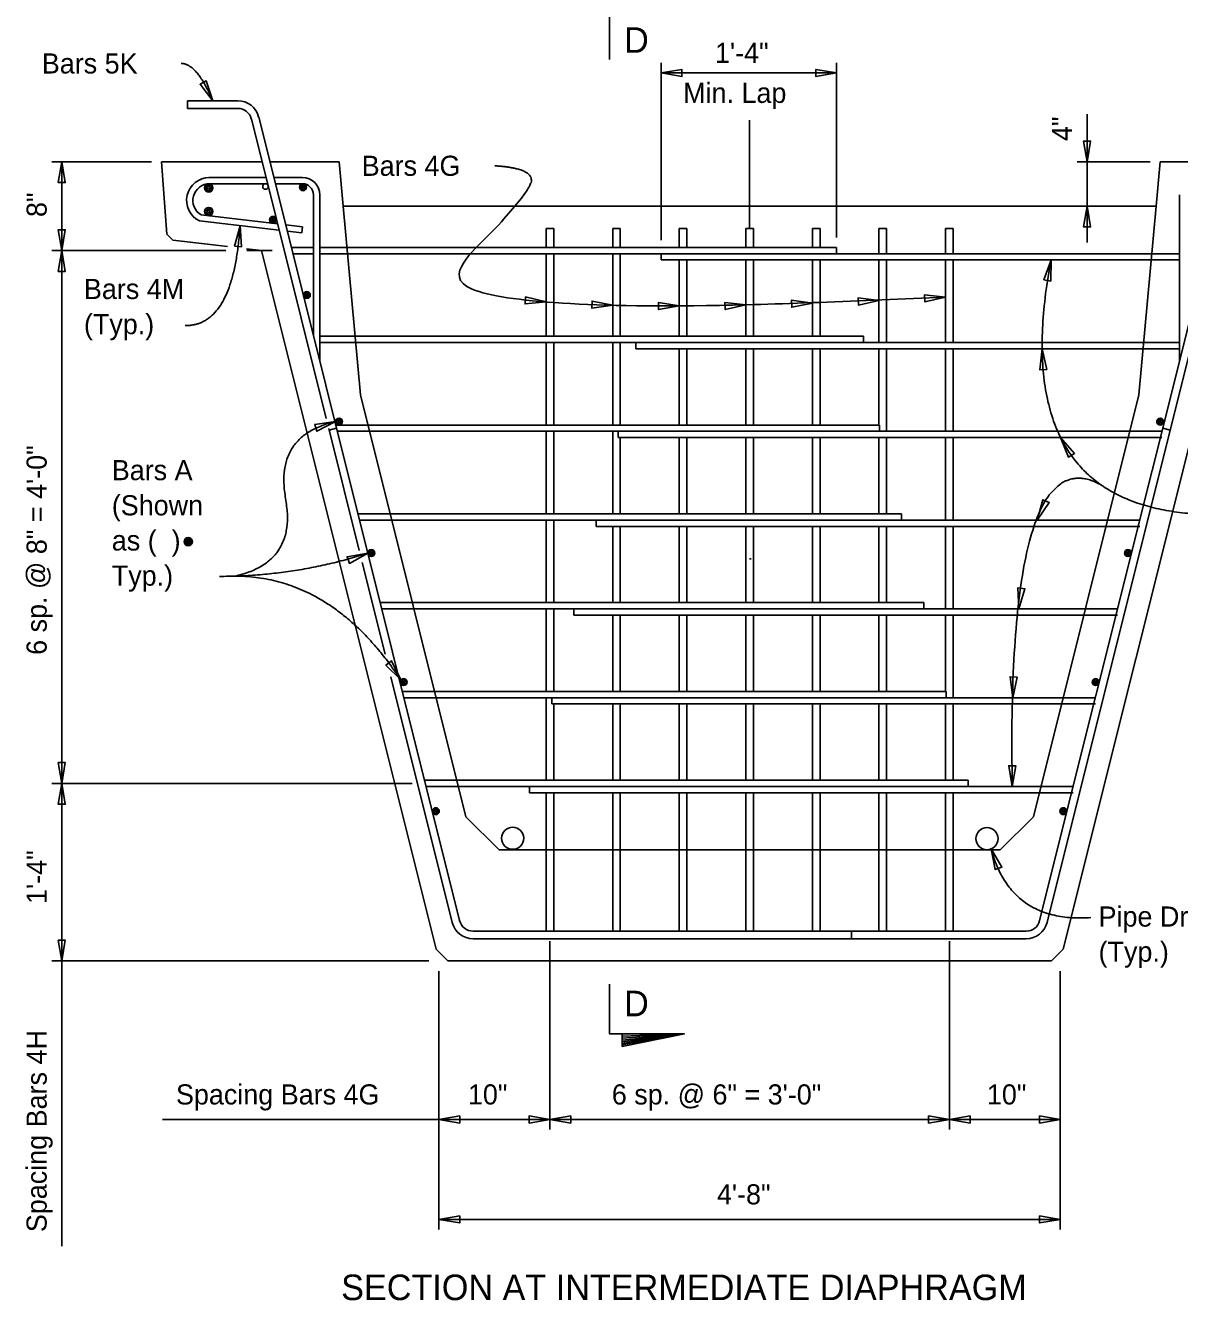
# Model space of a CAD drawing. Extents: x 120693.4 to 120747.1, y 120647.1 to 120670.1.
# Drawn here: x 120693.43 to 120702.1, y 120652.17 to 120661.74 of the extents above; entities that cross this region are included whole.
import ezdxf

# ---------------------------------------------------------------- set-up
doc = ezdxf.new("R2010")
doc.units = 0
for name, color, linetype in [('BeamConc', 7, 'Continuous'), ('BeamConc_h', 7, 'Continuous'), ('CL_Major', 7, 'Continuous'), ('Dimension', 7, 'Continuous'), ('Miscellaneous', 7, 'Continuous'), ('Rebar', 7, 'Continuous'), ('TextStructures', 7, 'Continuous')]:
    doc.layers.add(name, color=color, linetype=linetype)

msp = doc.modelspace()

# ---------------------------------------------------------------- linework, layer by layer
at = {"layer": 'BeamConc'}
for p, q in [((120694.456, 120660.7178), (120694.4948, 120660.1751)), ((120694.456, 120660.7178), (120695.2111, 120660.7178)), ((120695.2702, 120660.7178), (120695.7893, 120660.7178)), ((120695.8198, 120660.3845), (120695.7893, 120660.7178)), ((120701.9255, 120660.3845), (120701.956, 120660.7178)), ((120701.956, 120660.7178), (120702.4751, 120660.7178)), ((120695.8198, 120660.3845), (120701.9255, 120660.3845)), ((120694.5404, 120660.1294), (120694.4948, 120660.1751)), ((120694.5404, 120660.1294), (120694.9505, 120660.0812)), ((120695.0946, 120660.0642), (120695.206, 120660.0511)), ((120696.5172, 120654.8062), (120695.206, 120660.0511)), ((120701.2281, 120654.8062), (120702.5393, 120660.0511)), ((120696.6056, 120654.7178), (120696.5172, 120654.8062)), ((120701.1397, 120654.7178), (120701.2281, 120654.8062)), ((120696.6056, 120654.7178), (120701.1397, 120654.7178))]:
    msp.add_line(p, q, dxfattribs=at)
at = {"layer": 'BeamConc_h'}
for p, q in [((120695.9493, 120658.9678), (120695.8198, 120660.3845)), ((120701.7961, 120658.9678), (120701.9255, 120660.3845)), ((120696.7409, 120655.8011), (120695.9493, 120658.9678)), ((120701.0044, 120655.8011), (120701.7961, 120658.9678)), ((120696.7409, 120655.8011), (120696.9909, 120655.5511)), ((120701.0044, 120655.8011), (120700.7544, 120655.5511)), ((120696.9909, 120655.5511), (120700.7544, 120655.5511))]:
    msp.add_line(p, q, dxfattribs=at)
at = {"layer": 'CL_Major'}
for p, q in [((120698.8727, 120660.2178), (120698.8727, 120661.0292)), ((120698.8727, 120657.7357), (120698.885, 120657.7357))]:
    msp.add_line(p, q, dxfattribs=at)
at = {"layer": 'Dimension'}
for p, q in [((120698.2086, 120660.1281), (120698.2086, 120661.4601)), ((120699.5261, 120660.1502), (120699.5261, 120661.4601)), ((120698.2086, 120661.3845), (120699.5261, 120661.3845)), ((120701.4076, 120661.0752), (120701.4076, 120660.1113)), ((120694.3804, 120660.7178), (120693.6304, 120660.7178)), ((120693.706, 120660.7178), (120693.706, 120652.5766)), ((120701.8804, 120660.7178), (120701.3319, 120660.7178)), ((120694.9389, 120660.0511), (120693.6304, 120660.0511)), ((120695.2856, 120660.0511), (120695.0951, 120660.0511)), ((120696.3376, 120656.0511), (120693.6304, 120656.0511)), ((120697.3726, 120654.8661), (120697.3726, 120653.4522)), ((120700.3726, 120654.8661), (120700.3726, 120653.4522)), ((120696.4637, 120654.7178), (120693.6304, 120654.7178)), ((120696.5393, 120654.6421), (120696.5393, 120652.7022)), ((120701.206, 120654.6421), (120701.206, 120652.7022)), ((120697.914, 120654.1523), (120698.3827, 120654.1698)), ((120698.3827, 120654.1698), (120697.914, 120654.1373)), ((120697.914, 120654.1235), (120698.3827, 120654.1698)), ((120698.3827, 120654.1698), (120697.914, 120654.1098)), ((120697.914, 120654.0973), (120698.3827, 120654.1698)), ((120698.3827, 120654.1698), (120697.914, 120654.0873)), ((120694.4617, 120653.5278), (120701.206, 120653.5278)), ((120696.5393, 120652.7779), (120701.206, 120652.7779))]:
    msp.add_line(p, q, dxfattribs=at)
for points in [[(120697.8202, 120661.4861), (120697.8202, 120661.8611), (120698.3827, 120661.8611), (120697.914, 120661.9548), (120697.914, 120661.8611)], [(120697.8202, 120654.5448), (120697.8202, 120654.1698), (120698.3827, 120654.1698), (120697.914, 120654.076), (120697.914, 120654.1698)]]:
    msp.add_lwpolyline(points, dxfattribs=at)
for points in [[(120698.2085, 120661.3845), (120698.3642, 120661.3578), (120698.3642, 120661.4111)], [(120699.526, 120661.3845), (120699.3704, 120661.4111), (120699.3704, 120661.3578)], [(120694.8418, 120661.175), (120694.7444, 120661.2999), (120694.791, 120661.325)], [(120701.4072, 120660.7176), (120701.4339, 120660.8732), (120701.3806, 120660.8732)], [(120693.706, 120660.7177), (120693.6796, 120660.5615), (120693.7325, 120660.5615)], [(120701.4072, 120660.3843), (120701.3806, 120660.2286), (120701.4339, 120660.2286)], [(120693.706, 120660.0512), (120693.6796, 120660.2074), (120693.7325, 120660.2074)], [(120695.0456, 120660.2377), (120695.0565, 120660.0797), (120695.0038, 120660.0849)], [(120693.706, 120660.051), (120693.6796, 120659.8949), (120693.7325, 120659.8949)], [(120701.1366, 120659.9807), (120701.0828, 120659.8317), (120701.1349, 120659.8223)], [(120697.3441, 120659.6656), (120697.1903, 120659.7035), (120697.1863, 120659.6507)], [(120699.344, 120659.6573), (120699.187, 120659.6784), (120699.1888, 120659.6255)], [(120699.844, 120659.6768), (120699.6866, 120659.6953), (120699.6893, 120659.6424)], [(120700.344, 120659.7006), (120700.1866, 120659.719), (120700.1893, 120659.6662)], [(120697.8441, 120659.6412), (120697.6887, 120659.672), (120697.6872, 120659.6191)], [(120698.3441, 120659.6366), (120698.1875, 120659.6605), (120698.1883, 120659.6076)], [(120698.844, 120659.6432), (120698.6865, 120659.661), (120698.6895, 120659.6081)], [(120701.0697, 120659.3141), (120701.0517, 120659.1567), (120701.1045, 120659.1595)], [(120695.763, 120658.7673), (120695.606, 120658.7457), (120695.6219, 120658.6952)], [(120701.2084, 120658.6474), (120701.2675, 120658.5004), (120701.3126, 120658.528)], [(120701.0335, 120658.0278), (120701.1227, 120658.1587), (120701.0746, 120658.1808)], [(120696.0052, 120657.7801), (120695.8491, 120657.7529), (120695.8668, 120657.703)], [(120700.894, 120657.3611), (120700.9398, 120657.5127), (120700.8873, 120657.5194)], [(120696.253, 120656.8279), (120696.1832, 120656.9701), (120696.1403, 120656.9391)], [(120700.85, 120656.6944), (120700.8815, 120656.8496), (120700.8286, 120656.8513)], [(120693.706, 120656.0512), (120693.6796, 120656.2074), (120693.7325, 120656.2074)], [(120700.8448, 120656.0277), (120700.8714, 120656.1839), (120700.8185, 120656.1839)], [(120693.706, 120656.051), (120693.6796, 120655.8949), (120693.7325, 120655.8949)], [(120700.6871, 120655.5597), (120700.7674, 120655.4231), (120700.7179, 120655.4043)], [(120693.706, 120654.7177), (120693.7325, 120654.8739), (120693.6796, 120654.8739)], [(120696.539, 120653.5276), (120696.6947, 120653.5009), (120696.6947, 120653.5543)], [(120697.3727, 120653.5278), (120697.2165, 120653.5542), (120697.2165, 120653.5013)], [(120697.3726, 120653.5278), (120697.5288, 120653.5542), (120697.5288, 120653.5013)], [(120700.3727, 120653.5278), (120700.2165, 120653.5542), (120700.2165, 120653.5013)], [(120700.3726, 120653.5278), (120700.5288, 120653.5542), (120700.5288, 120653.5013)], [(120701.2057, 120653.5276), (120701.05, 120653.5543), (120701.05, 120653.5009)], [(120696.539, 120652.7777), (120696.6947, 120652.751), (120696.6947, 120652.8043)], [(120701.2057, 120652.7777), (120701.05, 120652.8043), (120701.05, 120652.751)]]:
    msp.add_lwpolyline(points, close=True, dxfattribs=at)
for points in [[(120694.8392, 120661.1761), (120694.721, 120661.4562), (120694.6028, 120661.4562)], [(120700.344, 120659.7006), (120696.2635, 120659.492), (120697.1739, 120660.4306), (120697.2782, 120660.667), (120696.9585, 120660.6879)], [(120695.0451, 120660.2378), (120694.9958, 120659.4842), (120694.6336, 120659.4883)], [(120701.1366, 120659.9808), (120700.7737, 120658.0694), (120702.3784, 120658.0694)], [(120695.0044, 120657.607), (120695.4741, 120657.7086), (120695.3013, 120658.6637), (120695.763, 120658.7673)], [(120700.8448, 120656.0277), (120700.7997, 120658.6696), (120701.5068, 120658.2958)], [(120694.8903, 120657.6052), (120695.4651, 120657.6052), (120696.0052, 120657.7801)], [(120695.0044, 120657.607), (120695.7368, 120657.607), (120696.2531, 120656.8269)], [(120700.6861, 120655.5593), (120700.8388, 120655.0002), (120701.4364, 120655.044)]]:
    msp.add_open_spline(points, degree=2, dxfattribs=at)
at = {"layer": 'Miscellaneous'}
for centre in [(120697.093, 120655.6393), (120700.6551, 120655.6361)]:
    msp.add_circle(centre, 0.0833, dxfattribs=at)
at = {"layer": 'Rebar'}
for p, q in [((120694.6502, 120661.1761), (120695.0282, 120661.1761)), ((120694.6502, 120661.1761), (120694.6502, 120661.1188)), ((120694.6502, 120661.1188), (120695.0282, 120661.1188)), ((120695.6932, 120658.7894), (120695.1305, 120661.0402)), ((120696.6945, 120655.0207), (120695.1861, 120661.0541)), ((120701.0509, 120655.0207), (120702.5605, 120661.059)), ((120701.1064, 120655.0068), (120702.6148, 120661.0402)), ((120695.2406, 120660.5997), (120694.8105, 120660.5997)), ((120695.2524, 120660.5528), (120694.8105, 120660.5528)), ((120695.5137, 120660.5997), (120695.2997, 120660.5997)), ((120695.5137, 120660.5528), (120695.3114, 120660.5528)), ((120695.597, 120659.4105), (120695.597, 120660.4695)), ((120695.6439, 120659.223), (120695.6439, 120660.4695)), ((120702.1015, 120659.223), (120702.1015, 120660.4695)), ((120694.7395, 120660.2738), (120695.3398, 120660.2032)), ((120694.7537, 120660.3193), (120695.3276, 120660.2518)), ((120695.3885, 120660.2446), (120695.5135, 120660.2299)), ((120695.4006, 120660.196), (120695.508, 120660.1834)), ((120695.5135, 120660.2299), (120695.508, 120660.1834)), ((120697.4014, 120660.2178), (120697.3441, 120660.2178)), ((120697.3441, 120660.0746), (120697.3441, 120660.2178)), ((120697.4014, 120660.0746), (120697.4014, 120660.2178)), ((120697.9014, 120660.2178), (120697.8441, 120660.2178)), ((120697.8441, 120660.0746), (120697.8441, 120660.2178)), ((120697.9014, 120660.0746), (120697.9014, 120660.2178)), ((120698.4014, 120660.2178), (120698.3441, 120660.2178)), ((120698.3441, 120660.0746), (120698.3441, 120660.2178)), ((120698.4014, 120660.0746), (120698.4014, 120660.2178)), ((120698.844, 120660.2178), (120698.9013, 120660.2178)), ((120698.844, 120660.0746), (120698.844, 120660.2178)), ((120698.9013, 120660.0746), (120698.9013, 120660.2178)), ((120699.344, 120660.2178), (120699.4013, 120660.2178)), ((120699.344, 120660.0746), (120699.344, 120660.2178)), ((120699.4013, 120660.0746), (120699.4013, 120660.2178)), ((120699.844, 120660.2178), (120699.9013, 120660.2178)), ((120699.844, 120660.0276), (120699.844, 120660.2178)), ((120699.9013, 120660.0276), (120699.9013, 120660.2178)), ((120700.344, 120660.2178), (120700.4013, 120660.2178)), ((120700.344, 120660.0276), (120700.344, 120660.2178)), ((120700.4013, 120660.0276), (120700.4013, 120660.2178)), ((120695.431, 120660.0746), (120695.597, 120660.0746)), ((120695.6439, 120660.0746), (120699.5261, 120660.0746)), ((120699.5261, 120660.0746), (120699.5261, 120660.0276)), ((120695.4427, 120660.0276), (120695.597, 120660.0276)), ((120695.6439, 120660.0276), (120702.1015, 120660.0276)), ((120697.3441, 120659.4079), (120697.3441, 120660.0276)), ((120697.4014, 120659.4079), (120697.4014, 120660.0276)), ((120697.8441, 120659.4079), (120697.8441, 120660.0276)), ((120697.9014, 120659.4079), (120697.9014, 120660.0276)), ((120698.2076, 120660.0277), (120698.2076, 120659.9807)), ((120698.2076, 120659.9807), (120702.1015, 120659.9807)), ((120698.3441, 120659.4079), (120698.3441, 120659.9807)), ((120698.4014, 120659.4079), (120698.4014, 120659.9807)), ((120698.844, 120659.4079), (120698.844, 120659.9807)), ((120698.9013, 120659.4079), (120698.9013, 120659.9807)), ((120699.344, 120659.4079), (120699.344, 120659.9807)), ((120699.4013, 120659.4079), (120699.4013, 120659.9807)), ((120699.844, 120659.3609), (120699.844, 120659.9807)), ((120699.9013, 120659.3609), (120699.9013, 120659.9807)), ((120700.344, 120659.3609), (120700.344, 120659.9807)), ((120700.4013, 120659.3609), (120700.4013, 120659.9807)), ((120695.6439, 120659.4079), (120699.7272, 120659.4079)), ((120699.7272, 120659.4079), (120699.7272, 120659.3609)), ((120695.6439, 120659.3609), (120702.1015, 120659.3609)), ((120697.3441, 120658.7413), (120697.3441, 120659.3609)), ((120697.4014, 120658.7413), (120697.4014, 120659.3609)), ((120697.8441, 120658.7413), (120697.8441, 120659.3609)), ((120697.9014, 120658.7413), (120697.9014, 120659.3609)), ((120698.0181, 120659.3611), (120698.0181, 120659.3141)), ((120698.0181, 120659.3141), (120702.1015, 120659.3141)), ((120698.3441, 120658.7413), (120698.3441, 120659.3141)), ((120698.4014, 120658.7413), (120698.4014, 120659.3141)), ((120698.844, 120658.7413), (120698.844, 120659.3141)), ((120698.9013, 120658.7413), (120698.9013, 120659.3141)), ((120699.344, 120658.7413), (120699.344, 120659.3141)), ((120699.4013, 120658.7413), (120699.4013, 120659.3141)), ((120699.844, 120658.7413), (120699.844, 120659.3141)), ((120699.9013, 120658.6943), (120699.9013, 120659.3141)), ((120700.344, 120658.6943), (120700.344, 120659.3141)), ((120700.4013, 120658.6943), (120700.4013, 120659.3141)), ((120695.7643, 120658.7413), (120699.8476, 120658.7413)), ((120699.8476, 120658.7413), (120699.8476, 120658.6943)), ((120695.9405, 120657.8002), (120695.7116, 120658.7159)), ((120695.7702, 120658.7178), (120695.7146, 120658.7039)), ((120695.7761, 120658.6943), (120701.9693, 120658.6943)), ((120697.3441, 120658.0746), (120697.3441, 120658.6943)), ((120697.4014, 120658.0746), (120697.4014, 120658.6943)), ((120697.8441, 120658.0746), (120697.8441, 120658.6943)), ((120697.8859, 120658.6944), (120697.8859, 120658.6474)), ((120697.8859, 120658.6474), (120701.9693, 120658.6474)), ((120697.9014, 120658.0746), (120697.9014, 120658.6474)), ((120698.3441, 120658.0746), (120698.3441, 120658.6474)), ((120698.4014, 120658.0746), (120698.4014, 120658.6474)), ((120698.844, 120658.0746), (120698.844, 120658.6474)), ((120698.9013, 120658.0746), (120698.9013, 120658.6474)), ((120699.344, 120658.0746), (120699.344, 120658.6474)), ((120699.4013, 120658.0746), (120699.4013, 120658.6474)), ((120699.844, 120658.0746), (120699.844, 120658.6474)), ((120699.9013, 120658.0746), (120699.9013, 120658.6474)), ((120700.344, 120658.0276), (120700.344, 120658.6474)), ((120700.4013, 120658.0276), (120700.4013, 120658.6474)), ((120701.9751, 120658.7178), (120702.0307, 120658.7039)), ((120695.931, 120658.0746), (120700.0143, 120658.0746)), ((120700.0143, 120658.0746), (120700.0143, 120658.0276)), ((120695.9427, 120658.0276), (120701.8026, 120658.0276)), ((120697.3441, 120657.4079), (120697.3441, 120658.0276)), ((120697.4014, 120657.4079), (120697.4014, 120658.0276)), ((120697.7193, 120658.0277), (120697.7193, 120657.9807)), ((120697.7193, 120657.9807), (120701.8026, 120657.9807)), ((120697.8441, 120657.4079), (120697.8441, 120657.9807)), ((120697.9014, 120657.4079), (120697.9014, 120657.9807)), ((120698.3441, 120657.4079), (120698.3441, 120657.9807)), ((120698.4014, 120657.4079), (120698.4014, 120657.9807)), ((120698.844, 120657.4079), (120698.844, 120657.9807)), ((120698.9013, 120657.4079), (120698.9013, 120657.9807)), ((120699.344, 120657.4079), (120699.344, 120657.9807)), ((120699.4013, 120657.4079), (120699.4013, 120657.9807)), ((120699.844, 120657.4079), (120699.844, 120657.9807)), ((120699.9013, 120657.4079), (120699.9013, 120657.9807)), ((120700.344, 120657.3609), (120700.344, 120657.9807)), ((120700.4013, 120657.3609), (120700.4013, 120657.9807)), ((120696.135, 120657.0222), (120695.9629, 120657.7105)), ((120696.0976, 120657.4079), (120700.181, 120657.4079)), ((120700.181, 120657.4079), (120700.181, 120657.3609)), ((120696.1094, 120657.3609), (120701.6359, 120657.3609)), ((120697.3441, 120656.7413), (120697.3441, 120657.3609)), ((120697.4014, 120656.7413), (120697.4014, 120657.3609)), ((120697.5526, 120657.3611), (120697.5526, 120657.3141)), ((120697.5526, 120657.3141), (120701.6359, 120657.3141)), ((120697.8441, 120656.7413), (120697.8441, 120657.3141)), ((120697.9014, 120656.7413), (120697.9014, 120657.3141)), ((120698.3441, 120656.7413), (120698.3441, 120657.3141)), ((120698.4014, 120656.7413), (120698.4014, 120657.3141)), ((120698.844, 120656.7413), (120698.844, 120657.3141)), ((120698.9013, 120656.7413), (120698.9013, 120657.3141)), ((120699.344, 120656.7413), (120699.344, 120657.3141)), ((120699.4013, 120656.7413), (120699.4013, 120657.3141)), ((120699.844, 120656.7413), (120699.844, 120657.3141)), ((120699.9013, 120656.7413), (120699.9013, 120657.3141)), ((120700.344, 120656.7413), (120700.344, 120657.3141)), ((120700.4013, 120656.6943), (120700.4013, 120657.3141)), ((120696.6389, 120655.0067), (120696.1777, 120656.8515)), ((120696.2643, 120656.7413), (120700.3476, 120656.7413)), ((120700.3476, 120656.7413), (120700.3476, 120656.6943)), ((120696.2761, 120656.6943), (120701.4693, 120656.6943)), ((120697.3441, 120656.0746), (120697.3441, 120656.6943)), ((120697.3859, 120656.6944), (120697.3859, 120656.6474)), ((120697.3859, 120656.6474), (120701.4693, 120656.6474)), ((120697.4014, 120656.0746), (120697.4014, 120656.6474)), ((120697.8441, 120656.0746), (120697.8441, 120656.6474)), ((120697.9014, 120656.0746), (120697.9014, 120656.6474)), ((120698.3441, 120656.0746), (120698.3441, 120656.6474)), ((120698.4014, 120656.0746), (120698.4014, 120656.6474)), ((120698.844, 120656.0746), (120698.844, 120656.6474)), ((120698.9013, 120656.0746), (120698.9013, 120656.6474)), ((120699.344, 120656.0746), (120699.344, 120656.6474)), ((120699.4013, 120656.0746), (120699.4013, 120656.6474)), ((120699.844, 120656.0746), (120699.844, 120656.6474)), ((120699.9013, 120656.0746), (120699.9013, 120656.6474)), ((120700.344, 120656.0746), (120700.344, 120656.6474)), ((120700.4013, 120656.0746), (120700.4013, 120656.6474)), ((120696.431, 120656.0746), (120700.5143, 120656.0746)), ((120700.5143, 120656.0746), (120700.5143, 120656.0276)), ((120696.4427, 120656.0276), (120701.3026, 120656.0276)), ((120697.2193, 120656.0277), (120697.2193, 120655.9807)), ((120697.2193, 120655.9807), (120701.3026, 120655.9807)), ((120697.3441, 120654.9417), (120697.3441, 120655.9807)), ((120697.4014, 120654.9417), (120697.4014, 120655.9807)), ((120697.8441, 120654.9417), (120697.8441, 120655.9807)), ((120697.9014, 120654.9417), (120697.9014, 120655.9807)), ((120698.3441, 120654.9417), (120698.3441, 120655.9807)), ((120698.4014, 120654.9417), (120698.4014, 120655.9807)), ((120698.844, 120654.9417), (120698.844, 120655.9807)), ((120698.9013, 120654.9417), (120698.9013, 120655.9807)), ((120699.344, 120654.9417), (120699.344, 120655.9807)), ((120699.4013, 120654.9417), (120699.4013, 120655.9807)), ((120699.844, 120654.9417), (120699.844, 120655.9807)), ((120699.9013, 120654.9417), (120699.9013, 120655.9807)), ((120700.344, 120654.9417), (120700.344, 120655.9807)), ((120700.4013, 120654.9417), (120700.4013, 120655.9807)), ((120696.7955, 120654.9417), (120700.9498, 120654.9417)), ((120699.6389, 120654.9417), (120699.6389, 120654.8844)), ((120696.7955, 120654.8844), (120700.9498, 120654.8844))]:
    msp.add_line(p, q, dxfattribs=at)
for centre, radius in [((120694.8102, 120660.5216), 0.0312), ((120694.8102, 120660.5216), 0.0215), ((120695.2361, 120660.532), 0.0208), ((120695.5185, 120660.5268), 0.026), ((120695.5185, 120660.5268), 0.0188), ((120694.8102, 120660.5216), 0.0103), ((120695.5185, 120660.5268), 0.0106), ((120695.5185, 120660.5268), 0.00453), ((120694.8102, 120660.3439), 0.0312), ((120694.8102, 120660.3439), 0.0209), ((120694.8102, 120660.3439), 0.00933), ((120695.2933, 120660.282), 0.026), ((120695.2933, 120660.282), 0.0188), ((120695.2933, 120660.282), 0.0106), ((120695.2933, 120660.282), 0.00453), ((120695.5468, 120659.7178), 0.026), ((120695.5468, 120659.7178), 0.0188), ((120695.5468, 120659.7178), 0.0106), ((120695.5468, 120659.7178), 0.00453), ((120695.789, 120658.7673), 0.026), ((120695.789, 120658.7673), 0.0188), ((120695.789, 120658.7673), 0.0106), ((120695.789, 120658.7673), 0.00453), ((120701.9563, 120658.7673), 0.026), ((120701.9563, 120658.7673), 0.0188), ((120701.9563, 120658.7673), 0.0106), ((120701.9563, 120658.7673), 0.00453), ((120694.6556, 120657.8659), 0.0312), ((120694.6556, 120657.8659), 0.0263), ((120694.6556, 120657.8659), 0.0213), ((120694.6556, 120657.8659), 0.0163), ((120694.6556, 120657.8659), 0.0112), ((120694.6556, 120657.8659), 0.00625), ((120696.0312, 120657.7801), 0.026), ((120696.0312, 120657.7801), 0.0188), ((120696.0312, 120657.7801), 0.0106), ((120696.0312, 120657.7801), 0.00453), ((120701.7141, 120657.7801), 0.026), ((120701.7141, 120657.7801), 0.0188), ((120701.7141, 120657.7801), 0.0106), ((120701.7141, 120657.7801), 0.00453), ((120696.2734, 120656.8113), 0.026), ((120696.2734, 120656.8113), 0.0188), ((120696.2734, 120656.8113), 0.0106), ((120696.2734, 120656.8113), 0.00453), ((120701.4719, 120656.8113), 0.026), ((120701.4719, 120656.8113), 0.0188), ((120701.4719, 120656.8113), 0.0106), ((120701.4719, 120656.8113), 0.00453), ((120696.5156, 120655.8425), 0.026), ((120696.5156, 120655.8425), 0.0188), ((120696.5156, 120655.8425), 0.0106), ((120701.2297, 120655.8425), 0.026), ((120701.2297, 120655.8425), 0.0188), ((120701.2297, 120655.8425), 0.0106), ((120696.5156, 120655.8425), 0.00453), ((120701.2297, 120655.8425), 0.00453)]:
    msp.add_circle(centre, radius, dxfattribs=at)
for centre, radius, start, end in [((120695.0282, 120661.0146), 0.1615, 14.03624, 90), ((120695.0282, 120661.0146), 0.1042, 14.03624, 90), ((120694.8157, 120660.4278), 0.1719, 90, 243.66403), ((120694.8157, 120660.4278), 0.125, 90, 240.23358), ((120695.5137, 120660.4695), 0.1302, 0, 90), ((120695.5137, 120660.4695), 0.0833, 0, 90), ((120696.7955, 120655.0459), 0.1615, 194.03624, 270), ((120696.7955, 120655.0459), 0.1042, 194.03624, 270), ((120700.9498, 120655.0459), 0.1042, 270, 345.96376), ((120700.9498, 120655.0459), 0.1615, 270, 345.96376)]:
    msp.add_arc(centre, radius, start, end, dxfattribs=at)

# ---------------------------------------------------------------- texts
at = {"layer": 'Dimension'}
for s, p in [('Bars 4M', (120693.8726, 120659.6873)), ('(Typ.)', (120693.8726, 120659.4233)), ('Bars A', (120694.0818, 120658.3272)), ('(Shown', (120694.0818, 120658.0632)), ('as (  )', (120694.0818, 120657.7992)), ('Typ.)', (120694.0818, 120657.5352)), ('Pipe Drain', (120701.4936, 120654.9759)), ('(Typ.)', (120701.4936, 120654.7119))]:
    msp.add_text(s, height=0.1512, dxfattribs=at).set_placement(p)
at = {"layer": 'TextStructures'}
for s, height, p in [('D', 0.192, (120697.9298, 120661.5359)), ('1\'-4"', 0.1512, (120698.6125, 120661.4601)), ('Bars 5K', 0.1512, (120693.5563, 120661.3804)), ('Min. Lap', 0.1512, (120698.3733, 120661.1595)), ('Bars 4G', 0.1512, (120695.959, 120660.6122)), ('D', 0.192, (120697.9298, 120654.3027)), ('Spacing Bars 4G', 0.1512, (120694.5638, 120653.6404)), ('10"', 0.1512, (120696.7567, 120653.6404)), ('6 sp. @ 6" = 3\'-0"', 0.1512, (120697.8375, 120653.6404)), ('10"', 0.1512, (120700.6548, 120653.6404)), ('4\'-8"', 0.1512, (120698.6271, 120652.8905)), ('SECTION AT INTERMEDIATE DIAPHRAGM', 0.192, (120695.8046, 120652.1716))]:
    msp.add_text(s, height=height, dxfattribs=at).set_placement(p)
for s, p in [('4"', (120701.2944, 120660.8733)), ('8"', (120693.5928, 120660.3029)), ('6 sp. @ 8" = 4\'-0"', (120693.5928, 120657.0159)), ('1\'-4"', (120693.5928, 120655.1461)), ('Spacing Bars 4H ', (120693.5928, 120652.6819))]:
    msp.add_text(s, height=0.1512, rotation=90, dxfattribs=at).set_placement(p)

doc.saveas('drawing.dxf')
